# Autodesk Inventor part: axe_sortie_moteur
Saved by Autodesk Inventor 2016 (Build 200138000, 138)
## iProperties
Created: 2013-08
Part Number: axe_sortie_moteur
Material: Générique
Document SubType Name: Modeling
Designer: hilarion
Density: 1 g/cm^3
Appearance: Par défaut
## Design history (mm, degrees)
node "axe_sortie_moteur1"
node "axe_sortie_moteur"
node "Base1"
